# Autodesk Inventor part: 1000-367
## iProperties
Created: 2007-03
Part Number: 1000-367
Document SubType Name: Modeling
Designer: Andy Moles
Material: Steel
Mass: 43.1734 g
Surface Area: 34.7689 cm^2
Volume: 5.4998 cm^3
Density: 7.85 g/cm^3
Author: Andy Moles
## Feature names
1. Base1
